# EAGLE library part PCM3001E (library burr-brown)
SoundPlus(TM) Stereo Audio Codec 18-bits, Serial Interface
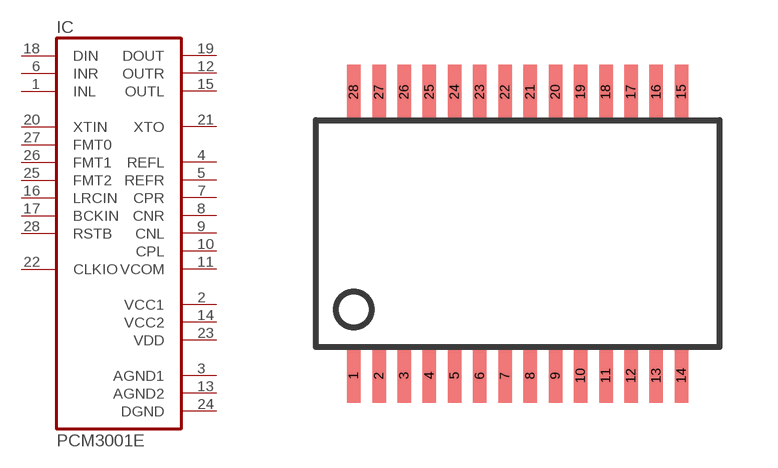
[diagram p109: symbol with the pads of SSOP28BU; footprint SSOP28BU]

Designator prefix IC

## PCM3001E (MF: TEXAS INSTRUMENTS; MPN: PCM3001E; OC_FARNELL: unknown; OC_NEWARK: 34K8600)  [SSOP28BU]
1  INL  in
2  VCC1  pwr
3  AGND1  pwr
4  REFL  pas
5  REFR  pas
6  INR  in
7  CPR  pas
8  CNR  pas
9  CNL  pas
10  CPL  pas
11  VCOM  pas
12  OUTR  out
13  AGND2  pwr
14  VCC2  pwr
15  OUTL  out
16  LRCIN  in
17  BCKIN  in
18  DIN  in
19  DOUT  out
20  XTIN  in
21  XTO  out
22  CLKIO
23  VDD  pwr
24  DGND  pwr
25  FMT2  in
26  FMT1  in
27  FMT0  in
28  RSTB  in

## Footprint SSOP28BU (pad centres in mm)
Small Shrink Outline Package
smd 0.348 x 1.397: 1 -4.225,-3.656; 2 -3.575,-3.656; 3 -2.925,-3.656; 4 -2.275,-3.656; 5 -1.625,-3.656; 6 -0.975,-3.656; 7 -0.325,-3.656; 8 0.325,-3.656; 9 0.975,-3.656; 10 1.625,-3.656; 11 2.275,-3.656; 12 2.925,-3.656; 13 3.575,-3.656; 14 4.225,-3.656; 15 4.225,3.656; 16 3.575,3.656; 17 2.925,3.656; 18 2.275,3.656; 19 1.625,3.656; 20 0.975,3.656; 21 0.325,3.656; 22 -0.325,3.656; 23 -0.975,3.656; 24 -1.625,3.656; 25 -2.275,3.656; 26 -2.925,3.656; 27 -3.575,3.656; 28 -4.225,3.656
